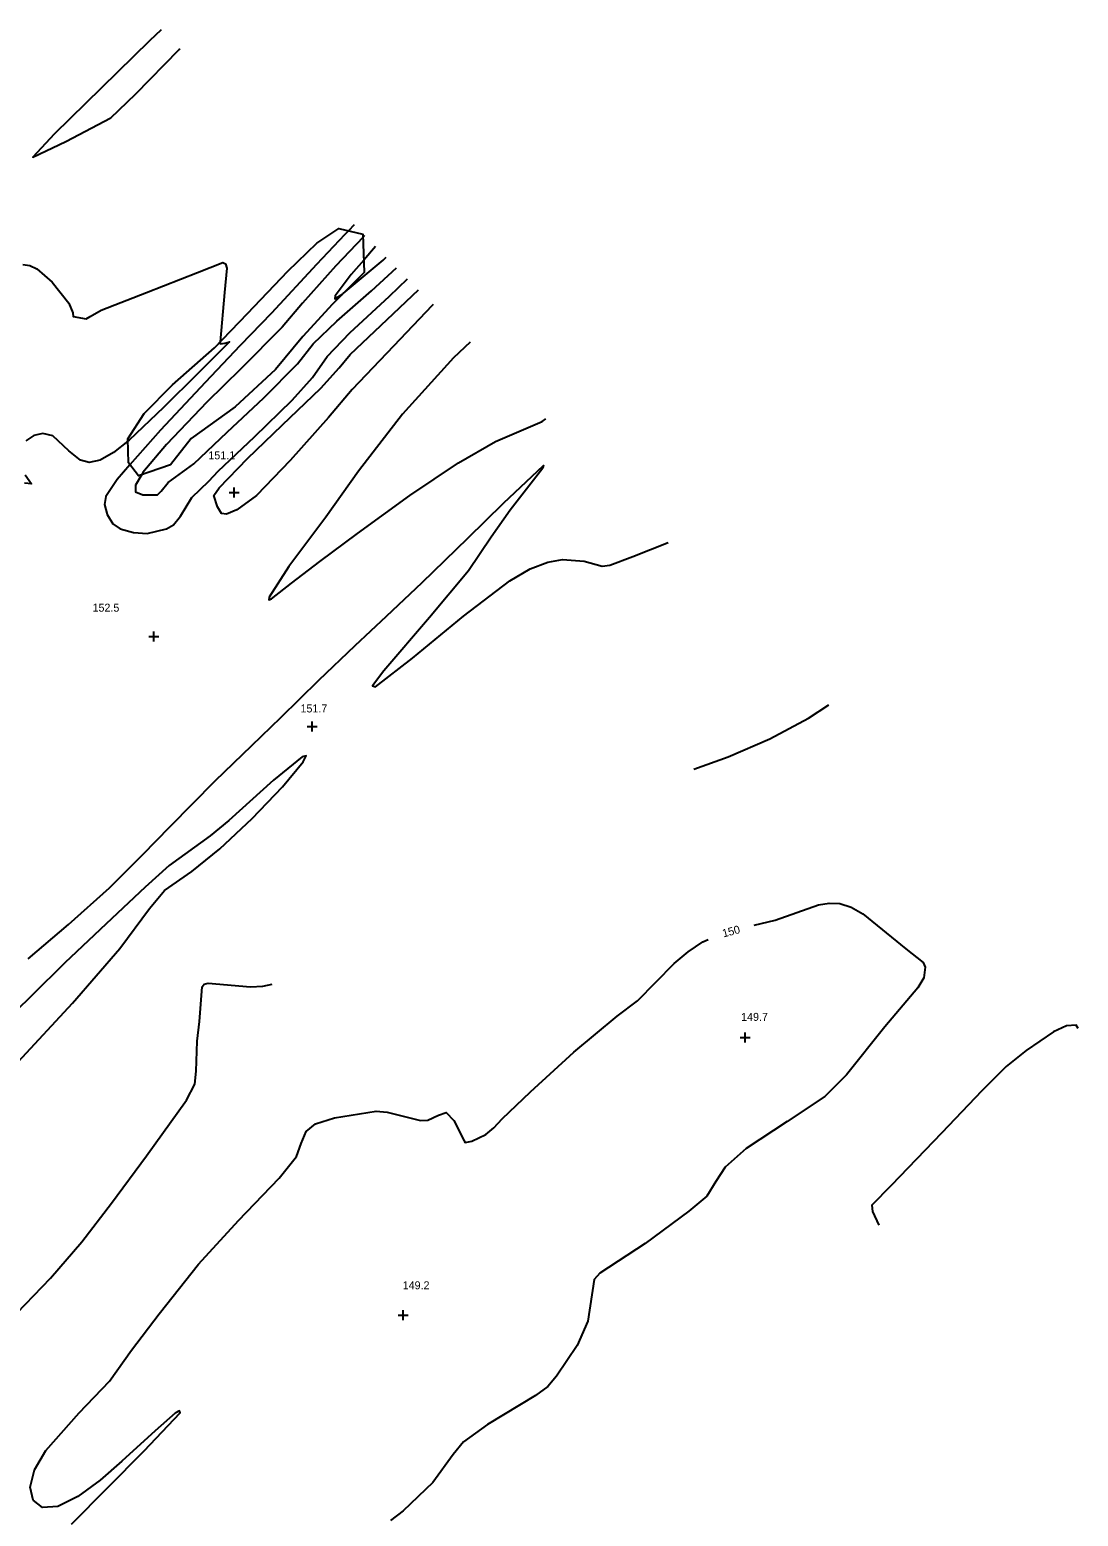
# Model space of a CAD drawing. Extents: x 1467615 to 2003689, y 770235 to 1108726.
# Drawn here: x 2002231.5 to 2002493.5, y 772192.1 to 772563.6 of the extents above; entities that cross this region are included whole.
import ezdxf

# ---------------------------------------------------------------- set-up
doc = ezdxf.new("R2010")
doc.units = 0
for name, color, linetype in [('RD_DTM_Major1', 7, 'Continuous'), ('RD_DTM_Major1_Lbl', 7, 'Continuous'), ('RD_DTM_Major2', 7, 'Continuous'), ('RD_DTM_Minor1', 7, 'Continuous'), ('RD_DTM_Minor2', 7, 'Continuous'), ('RD_DTM_Obscure', 7, 'Continuous'), ('RD_DTM_Spot_Elev', 7, 'Continuous')]:
    doc.layers.add(name, color=color, linetype=linetype)

msp = doc.modelspace()

# ---------------------------------------------------------------- linework, layer by layer
at = {"layer": 'RD_DTM_Major1'}
msp.add_line((2002317.95, 772509.42), (2002315, 772506.03), dxfattribs=at)
for points in [[(2002309.82, 772497.69), (2002319.83, 772506.05), (2002320.57, 772506.78)], [(2002412.49, 772339.79), (2002417.75, 772341.12), (2002428.58, 772344.92), (2002431.23, 772345.36), (2002433.96, 772345.25), (2002436.78, 772344.37), (2002439.71, 772342.63), (2002450.39, 772333.92), (2002454.76, 772330.52), (2002455.24, 772329.32), (2002454.94, 772326.65), (2002453.39, 772324.13), (2002445.18, 772314.45), (2002435.64, 772302.42), (2002430.2, 772297.04), (2002420.81, 772290.75), (2002410.53, 772284.03), (2002405.28, 772279.35), (2002402.93, 772275.73), (2002400.68, 772272.06), (2002396.24, 772268.32), (2002385.26, 772260.31), (2002373.97, 772252.85), (2002372.56, 772251.26), (2002370.96, 772240.88), (2002368.26, 772234.76), (2002363.13, 772227.11), (2002360.93, 772224.49), (2002357.87, 772222.29), (2002345.89, 772215.07), (2002339.89, 772210.68), (2002337.3, 772207.54), (2002332.26, 772200.53), (2002324.83, 772193.46), (2002321.64, 772191.02)], [(2002241.97, 772190.13), (2002250.97, 772199.22), (2002260.12, 772208.44), (2002269.14, 772217.98), (2002268.92, 772218.46), (2002267.83, 772217.84), (2002262.85, 772213.44), (2002254.57, 772205.84), (2002249.08, 772201.14), (2002243.52, 772197.06), (2002238.55, 772194.55), (2002234.74, 772194.31), (2002232.37, 772196.09), (2002231.62, 772199.38), (2002232.69, 772203.7), (2002235.58, 772208.54), (2002243.87, 772217.93), (2002251.41, 772225.84), (2002256.98, 772233.62), (2002263.85, 772242.71), (2002273.7, 772255.08), (2002283.67, 772266.04), (2002293.8, 772276.56), (2002298.18, 772282.03), (2002299.34, 772285.25), (2002300.58, 772288.28), (2002302.89, 772290.16), (2002307.7, 772291.71), (2002318.1, 772293.34), (2002320.83, 772293.1), (2002329.17, 772291.05), (2002331.01, 772291.1), (2002333.62, 772292.38), (2002335.53, 772293.01), (2002337.5, 772291), (2002340.1, 772285.89), (2002340.32, 772285.47), (2002341.95, 772285.81), (2002345.47, 772287.48), (2002347.44, 772289.19), (2002349.53, 772291.42), (2002356.65, 772298.2), (2002367.5, 772308.08), (2002378.29, 772317.08), (2002383.4, 772320.96), (2002392.53, 772330.24), (2002396, 772333.2), (2002399.73, 772335.69), (2002401.01, 772336.28)]]:
    msp.add_lwpolyline(points, dxfattribs=at)
at = {"layer": 'RD_DTM_Major2'}
msp.add_lwpolyline([(2002315, 772506.03), (2002311.86, 772502.43), (2002307.84, 772497.16), (2002307.77, 772496.37), (2002309.64, 772497.54), (2002309.82, 772497.69)], dxfattribs=at)
at = {"layer": 'RD_DTM_Minor1'}
for p, q in [((2002312.58, 772514.85), (2002311.16, 772513.35)), ((2002315.2, 772512.2), (2002314.8, 772511.78))]:
    msp.add_line(p, q, dxfattribs=at)
for points in [[(2002264.37, 772563.63), (2002261.41, 772560.82), (2002249.41, 772549.13), (2002237.62, 772537.54), (2002232.27, 772531.8), (2002240.55, 772535.69), (2002251.79, 772541.63), (2002257.94, 772547.54), (2002268.85, 772558.68), (2002269.03, 772558.92)], [(2002229.8, 772504.91), (2002231.53, 772504.66), (2002233.32, 772503.83), (2002237.11, 772500.5), (2002241.25, 772495.26), (2002242.29, 772492.9), (2002242.41, 772491.96), (2002245.6, 772491.34), (2002246.62, 772491.97), (2002249.33, 772493.54), (2002260.68, 772497.98), (2002273.41, 772502.98), (2002279.73, 772505.46), (2002280.46, 772505.11), (2002280.73, 772504.01), (2002280.17, 772497.99), (2002279.1, 772485.61)], [(2002256.55, 772454.86), (2002253.33, 772451.22), (2002250.49, 772446.99), (2002250.22, 772444.97), (2002250.9, 772442.44), (2002252.32, 772440.17), (2002254.12, 772438.86), (2002257.45, 772437.93), (2002260.84, 772437.76), (2002265.73, 772438.85), (2002267.44, 772439.87), (2002269.17, 772442.02), (2002272.01, 772446.7), (2002276.24, 772450.83), (2002278.64, 772453.3), (2002287.66, 772461.88), (2002297.06, 772471.02), (2002302.15, 772476.73), (2002305.81, 772481.92), (2002311.46, 772487.88), (2002321.4, 772497.04), (2002325.92, 772501.36)], [(2002259.49, 772452.43), (2002257.96, 772449.81), (2002257.93, 772448.13), (2002259.75, 772447.36), (2002263.43, 772447.36), (2002264.36, 772448.33), (2002266.09, 772450.48), (2002272.49, 772455.12), (2002280.81, 772463.05), (2002289.98, 772471.63), (2002298.44, 772480.11), (2002302.33, 772485.16), (2002308.21, 772490.75), (2002316.92, 772498.38), (2002323.17, 772504.15)], [(2002332.28, 772494.93), (2002332.06, 772494.69), (2002322.41, 772484.54), (2002312.11, 772473.67), (2002306.15, 772466.7), (2002296.63, 772456), (2002288.19, 772447.18), (2002283.26, 772443.62), (2002280.64, 772442.59), (2002279.44, 772442.74), (2002278.41, 772444.36), (2002277.55, 772447.21), (2002278.81, 772449.13), (2002285.89, 772456.48), (2002294.62, 772464.78), (2002304.26, 772474.01), (2002308.85, 772479.1), (2002311.57, 772482.42), (2002320.86, 772491.23), (2002328.62, 772498.63)], [(2002341.53, 772485.58), (2002337.41, 772481.66), (2002324.64, 772467.54), (2002313.66, 772453.28), (2002305.53, 772441.79), (2002296.22, 772429.5), (2002291.31, 772421.82), (2002291.22, 772421.18), (2002291.94, 772421.43), (2002296.95, 772425.31), (2002304, 772430.69), (2002313.44, 772437.72), (2002326.46, 772447.2), (2002338.64, 772455.41), (2002347.87, 772460.69), (2002359.52, 772465.74), (2002360.48, 772466.4)], [(2002256.05, 772460.81), (2002252.48, 772457.94), (2002249.13, 772456.02), (2002246.39, 772455.5), (2002244.22, 772456.05), (2002241.31, 772458.42), (2002237.25, 772462.12), (2002234.77, 772462.69), (2002232.57, 772462.24), (2002230.53, 772460.9)], [(2002231.13, 772331.38), (2002241.19, 772340.03), (2002251.42, 772349.18), (2002259.67, 772357.43), (2002266.58, 772364.47), (2002277.84, 772375.91), (2002286.97, 772384.7), (2002294.27, 772391.74), (2002303.75, 772401.04), (2002312.79, 772409.7), (2002320.63, 772417.08), (2002329.57, 772425.5), (2002340.96, 772436.58), (2002349.86, 772445.28), (2002359.89, 772454.71), (2002359.69, 772454.08), (2002351.58, 772443.57), (2002346.79, 772436.82), (2002341.18, 772428.4), (2002331.42, 772416.69), (2002319.97, 772403.39), (2002317.2, 772399.67), (2002317.95, 772399.42), (2002327.14, 772406.53), (2002339.86, 772417.1), (2002351.49, 772425.89), (2002356.54, 772428.85), (2002360.93, 772430.56), (2002364.64, 772431.25), (2002370.01, 772430.77), (2002374.58, 772429.56), (2002376.5, 772429.84), (2002382.25, 772431.98), (2002391.03, 772435.49)], [(2002230.35, 772452.4), (2002231.93, 772450.17), (2002230.24, 772450.3)], [(2002397.45, 772378.86), (2002406.06, 772381.92), (2002416.48, 772386.41), (2002426.1, 772391.55), (2002431.19, 772394.87)], [(2002228.61, 772305.7), (2002242.2, 772320.34), (2002254.07, 772334.02), (2002261.44, 772344.03), (2002265.23, 772348.52), (2002272.03, 772353.28), (2002279, 772358.93), (2002287.09, 772366.45), (2002294.7, 772374.39), (2002299.83, 772380.69), (2002300.57, 772382.18), (2002299.56, 772381.91), (2002292.46, 772376.08), (2002281.27, 772365.96), (2002276.58, 772362.12)], [(2002276.58, 772362.12), (2002266.32, 772354.73), (2002260.37, 772349.29), (2002252.03, 772341.49), (2002240.26, 772330.39), (2002232.01, 772322.25), (2002223.95, 772314.38), (2002215.1, 772305.69), (2002204.66, 772295.53), (2002195.07, 772286.9), (2002187.09, 772278.99), (2002177.81, 772269.45), (2002167.77, 772259.31), (2002160.35, 772251.99), (2002150.56, 772242.4), (2002138.51, 772230.74), (2002129.51, 772222.2), (2002118.86, 772212.25), (2002110.3, 772203.95), (2002099.77, 772193.37), (2002090.79, 772184.17)], [(2002178.23, 772184.86), (2002190.56, 772199.51), (2002202.6, 772214.24), (2002214.41, 772228.14), (2002226.27, 772240.78), (2002236.67, 772251.63), (2002244.51, 772260.7), (2002251.91, 772270.34), (2002260.72, 772282.21), (2002270.71, 772296.09), (2002272.81, 772300.06), (2002273.13, 772303.37), (2002273.35, 772310.84), (2002273.96, 772315.75), (2002274.57, 772324.38), (2002275.07, 772325.12), (2002276.06, 772325.35), (2002286.66, 772324.42), (2002289.78, 772324.56), (2002292.07, 772325.07)], [(2002493.51, 772314.04), (2002492.99, 772314.84), (2002490.6, 772314.69), (2002487.33, 772313.16), (2002480.47, 772308.54), (2002475.52, 772304.51), (2002469.44, 772298.43), (2002459.43, 772287.93), (2002446.74, 772274.76), (2002441.94, 772269.89), (2002442.13, 772268.29), (2002443.7, 772264.83)]]:
    msp.add_lwpolyline(points, dxfattribs=at)
at = {"layer": 'RD_DTM_Minor2'}
for points in [[(2002311.16, 772513.35), (2002310.28, 772512.43), (2002303.16, 772504.93), (2002291.89, 772492.81), (2002284.13, 772484.68), (2002275.38, 772475.48), (2002264.21, 772463.53), (2002256.55, 772454.86)], [(2002314.8, 772511.78), (2002308.04, 772504.64), (2002299.68, 772495.3), (2002294.59, 772489.33), (2002284.25, 772478.86), (2002275.8, 772470.53), (2002265.69, 772459.98), (2002259.8, 772452.95), (2002259.49, 772452.43)], [(2002279.1, 772485.61), (2002279.06, 772485.1), (2002280.28, 772485.3), (2002281.46, 772485.65), (2002273.49, 772477.7), (2002264.91, 772469.21), (2002256.32, 772461.02), (2002256.05, 772460.81)]]:
    msp.add_lwpolyline(points, dxfattribs=at)
at = {"layer": 'RD_DTM_Obscure'}
msp.add_lwpolyline([(2002315.11, 772502.93), (2002307.17, 772495.06), (2002299.79, 772486.96), (2002292.89, 772478.73), (2002282.81, 772469.39), (2002271.87, 772461.46), (2002266.73, 772454.92), (2002258.71, 772452.16), (2002256.16, 772455.35), (2002256.04, 772461.34), (2002260.11, 772467.68), (2002267.22, 772474.84), (2002277.68, 772484.15), (2002285.96, 772492.67), (2002296.04, 772503.26), (2002303.24, 772510.31), (2002308.72, 772513.93), (2002314.77, 772512.5), (2002315.11, 772502.93)], dxfattribs=at)
at = {"layer": 'RD_DTM_Spot_Elev'}
for p, q in [((2002282.62, 772446.71), (2002282.62, 772449.21)), ((2002281.37, 772447.96), (2002283.87, 772447.96)), ((2002261.24, 772411.97), (2002263.74, 772411.97)), ((2002262.49, 772410.72), (2002262.49, 772413.22)), ((2002300.86, 772389.5), (2002303.36, 772389.5)), ((2002302.11, 772388.25), (2002302.11, 772390.75)), ((2002408.99, 772311.75), (2002411.49, 772311.75)), ((2002410.24, 772310.5), (2002410.24, 772313)), ((2002323.55, 772242.32), (2002326.05, 772242.32)), ((2002324.8, 772241.07), (2002324.8, 772243.57))]:
    msp.add_line(p, q, dxfattribs=at)

# ---------------------------------------------------------------- texts
at = {"layer": 'RD_DTM_Major1_Lbl'}
msp.add_text('150', height=2, rotation=14.8304, dxfattribs=at).set_placement((2002404.86, 772336.75))
at = {"layer": 'RD_DTM_Spot_Elev'}
for s, p in [('151.1', (2002276.15, 772456.25)), ('152.5', (2002247.21, 772418.18)), ('151.7', (2002299.17, 772393)), ('149.7', (2002409.27, 772315.91)), ('149.2', (2002324.71, 772248.82))]:
    msp.add_text(s, height=2, dxfattribs=at).set_placement(p)

doc.saveas('drawing.dxf')
